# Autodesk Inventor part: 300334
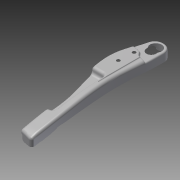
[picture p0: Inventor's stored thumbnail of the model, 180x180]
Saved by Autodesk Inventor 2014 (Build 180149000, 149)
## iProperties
Created: 2007-11
Part Number: 300334
Document SubType Name: Modeling
Designer: TH
Density: 7.85 g/cm^3
Mass: 603.841 g
Surface Area: 1574.23 cm^2
Volume: 76.9224 cm^3
Material: Steel
Description: RIGHT SIDE BACK MEMBER
Appearance: Steel
Component Category: Back Component
Author: TH
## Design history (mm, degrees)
workplane "Work Plane2"
sketch "Sketch2"
  geometry: L1 (50.438, -236.247)-(-305.503, 567.045) reference; L2 (295.506, 71.309)-(-341.064, -210.757) reference; L3 (-55.255, -84.114)-(-67.991, -55.371); L4 (-9.077, -101.935)-(-4.472, -99.894); L5 (15.931, -62.906)-(3.489, 23.045); L6 (-276.253, 429.962)-(-219.046, 442.719); L7 (-219.046, 442.719)-(-213.25, 429.637); L8 (-276.253, 429.962)-(-270.592, 416.127); A1 r 35 centre (-18.708, -67.92) between (-4.472, -99.894) and (15.931, -62.906); A2 r 35 centre (-23.256, -69.935) between (-55.255, -84.114) and (-9.077, -101.935); 10 further points
  constraints: 12 end point, 4 point on circle, 3 tangent, 2 centre point, 2 perpendicular, 2 point on line, 1 parallel, 17 other
  dimensions: "d0" = 35 radius of A2; "d1" = 35 radius of A1; "d2" = 4.97386 distance from line of A1.centre L1; "d4" = 542 distance from line of A1.centre L6; "d110" = 80.3179 deg angle of L8 L6; "d111" = 78.6722 deg angle of L7 L6
extrude "Extrusion1" new body sketch "Sketch2" distance "d5" = 82.31137; taper "d6" = 0 deg
fillet "Fillet1" dims "d7" = 11
workplane "Work Plane3"
sketch "Sketch4"
  geometry: L1 (-74.175, -82.311)-(-533.712, -82.311) reference; L2 (-533.712, 0)-(-533.712, -82.311) reference; L3 (-533.712, 0)-(-74.175, 0) reference; L4 (-74.175, 0)-(-74.175, -82.311) reference; L5 (-556.972, 0)-(-556.972, -82.311) reference; L6 (-556.972, -82.311)-(-556.972, -51.085); L7 (-556.972, -51.085)-(-546.972, -45.311); L8 (-546.972, -45.311)-(-542.696, -44.166); L9 (-549.79, -82.311)-(-556.972, -82.311) reference; L10 (35, 0)-(35, -82.311) reference; L11 (35, 0)-(-224.031, 0); L12 (-224.031, 0)-(-224.031, 20.09); L13 (-224.031, 20.09)-(-556.972, 20.09); L14 (-556.972, -51.085)-(-556.972, 20.09); L15 (-556.972, -51.085)-(-561.972, -53.972); L16 (-561.972, -53.972)-(-561.972, 20.09); L17 (-561.972, 20.09)-(-556.972, 20.09); 6 further points
  constraints: 20 end point, 3 perpendicular, 2 parallel, 2 point on line, 1 collinear, 1 horizontal, 9 other
  dimensions: "d9" = 60 deg angle of L7 L6; "d10" = 10 distance from line of L7.end L5; "d11" = 37 distance from line of L7.end L9; "d12" = 15 deg angle of L7 L8; "d13" = 14.27543 distance from line of L5 L8.end; "d29" = 5 distance between parallel lines of L16 L14
extrude "Extrusion2" cut sketch "Sketch4" stored distance "d14" = 82.31137; taper "d15" = 0 deg
sketch "Sketch5"
  geometry: L1 (-419, -38.349)-(-215.75, -22.71); L2 (-211.5, 0)-(-215.75, -22.71); L3 (-419, -38.349)-(-438.424, -22.843); L4 (-224.031, 0)-(-74.175, 0) reference; L5 (0, 20.844)-(0, -56.014) reference; L6 (-655.497, 0)-(109.25, 0) reference; 2 further points
  constraints: 6 end point, 1 point on line, 2 other
  dimensions: "d16" = 10.6 deg angle of L5 L2; "d17" = 211.5 distance from line of L5 L2.start; "d18" = 215.75 distance from line of L5 L1.end; "d19" = 75 deg angle of L2 L1; "d20" = 43 deg angle of L1 L3; "d21" = 419 distance from line of L5 L1.start
extrude "Extrusion3" cut sketch "Sketch5" distance "d22" = 75; taper "d23" = 0 deg
fillet "Fillet2" dims "d24" = 12
fillet "Fillet3" dims "d25" = 12
fillet "Fillet4" dims "d26" = 12
fillet "Fillet5" dims "d27" = 10
fillet "Fillet6" dims "d28" = 12
sketch "Sketch6"
  geometry: L1 (55.255, 84.114)-(67.991, 55.371) reference; L2 (4.472, 99.894)-(9.077, 101.935) reference; L3 (-3.489, -23.045)-(-15.931, 62.906) reference; L4 (86.496, 10.386)-(50.182, 5.126); L5 (50.182, 5.126)-(30.756, 15.263); L6 (30.756, 15.263)-(-7.798, 6.721); A1 r 35 centre (23.256, 69.935) between (55.255, 84.114) and (9.077, 101.935) reference; A2 r 35 centre (18.708, 67.92) between (4.472, 99.894) and (-15.931, 62.906) reference; 2 further points
  constraints: 6 end point, 1 point on line, 2 other
  dimensions: "d30" = 68 distance from line of L4 point (23.256, 69.935); "d31" = 55 distance from line of A1.centre L6; "d32" = 45 distance from line of A1.centre L5; "d34" = 7.5 horizontal distance of A1.centre L5.end; "d35" = 63.24061 horizontal distance of point (23.256, 69.935) L4.start; "d96" = 64.80946 vertical distance of L4.end A1.centre
extrude "Extrusion4" cut sketch "Sketch6" distance "d36" = 7.2; taper "d37" = 0 deg
fillet "Fillet7" dims "d38" = 12
fillet "Fillet10" dims "d41" = 5
fillet "Fillet11" dims "d42" = 11
fillet "Fillet13" dims "d44" = 4
fillet "Fillet14" dims "d45" = 4
sketch "Sketch7"
  geometry: C1 r 3 at (-8.5, 0); 1 further point
  constraints: 1 centre point
  dimensions: "d47" = 6 diameter of C1; "d48" = 8.5 distance of C1.centre point (0, 0)
extrude "Extrusion5" cut sketch "Sketch7" distance "d49" = 250; taper "d50" = 0 deg
sketch "Sketch9"
  geometry: L1 (0, 98.835)-(0, -16.829) reference; L2 (8.5, 0)-(8.5, 3); L3 (8.5, 0)-(5.5, 0); A1 r 3 centre (8.5, 0) between (8.5, 3) and (5.5, 0); 1 further point
  constraints: 4 end point, 2 point on circle, 1 centre point
  dimensions: "d52" = 3 radius of A1; "d53" = 90 deg angle of L1 L3; "d54" = 90 deg angle of L3 L2
revolve "Revolution1" sketch "Sketch9" stored, may be unused: angle "d55" = 90 deg
fillet "Fillet15" dims "d56" = 2
shell "Shell1" dims "d46" = 1
sketch "Sketch10"
  geometry: L1 (-482.932, -70.761)-(-510.571, -76.746) reference; L2 (-74.175, -82.311)-(-533.712, -82.311) reference; L3 (-539.005, -82.311)-(-549.79, -82.311) reference; L4 (0, -12.2)-(35, -12.2) reference; L5 (0, -12.2)-(0, -82.311) reference; L6 (0, -82.311)-(35, -82.311) reference; L7 (35, -12.2)-(35, -82.311) reference; L8 (35, -42.156)-(32.139, -42.156); L9 (35, -42.156)-(35, -90.815); L10 (35, -90.815)-(-545.613, -90.815); L11 (-545.613, -90.815)-(-545.613, -82.311); 22 further points
  constraints: 8 end point, 4 point on line, 2 perpendicular, 1 horizontal, 1 parallel, 19 other
extrude "Extrusion6" cut sketch "Sketch10" stored distance "d57" = 250; taper "d58" = 0 deg
sketch "Sketch11"
  geometry: L1 (27.137, -86.167)-(27.137, -34.343); L2 (19.355, -26.346)-(-70.705, -23.886); L3 (-72.495, -23.675)-(-114.778, -14.758); L4 (-116.568, -14.547)-(-150.782, -13.612); L5 (-154.205, -14.117)-(-212.597, -33.497); L6 (-213.236, -33.663)-(-224.191, -35.75); L7 (-224.708, -35.82)-(-458.639, -55.447); L8 (-462.612, -56.644)-(-470.617, -61.035); L9 (-473.169, -62.009)-(-531.249, -75.46); L10 (-537.377, -70.589)-(-537.377, -61.915); L11 (-543.505, -57.044)-(-561.7, -61.258); L12 (-561.7, -61.258)-(-561.7, -86.167); L13 (-561.7, -86.167)-(27.137, -86.167); A1 r 5 centre (-532.377, -70.589) between (-537.377, -70.589) and (-531.249, -75.46); A2 r 5 centre (-542.377, -61.915) between (-537.377, -61.915) and (-543.505, -57.044); A3 r 10 centre (-475.426, -52.266) between (-473.169, -62.009) and (-470.617, -61.035); A4 r 10 centre (-457.803, -65.412) between (-458.639, -55.447) and (-462.612, -56.644); A5 r 5 centre (-225.127, -30.838) between (-224.708, -35.82) and (-224.191, -35.75); A6 r 5 centre (-214.172, -28.752) between (-213.236, -33.663) and (-212.597, -33.497); A7 r 10 centre (-116.841, -24.543) between (-114.778, -14.758) and (-116.568, -14.547); A8 r 10 centre (-151.055, -23.608) between (-150.782, -13.612) and (-154.205, -14.117); A9 r 10 centre (-70.432, -13.89) between (-72.495, -23.675) and (-70.705, -23.886); A10 r 8 centre (19.137, -34.343) between (27.137, -34.343) and (19.355, -26.346); 11 further points
  constraints: 26 end point, 20 point on circle, 20 point on line, 20 tangent, 10 centre point, 7 equal radius, 4 parallel, 1 perpendicular, 1 vertical
  dimensions: "d59" = 27.13681 distance from line of L1 point (0, 0); "d60" = 71.60954 horizontal distance of point (-71.61, -23.862) point (0, 0); "d61" = 115.66329 horizontal distance of point (-115.663, -14.571) point (0, 0); "d62" = 152.53802 horizontal distance of point (-152.538, -13.564) point (0, 0); "d63" = 212.91121 horizontal distance of point (-212.911, -33.601) point (0, 0); "d64" = 224.4479 horizontal distance of point (-224.448, -35.799) point (0, 0); "d65" = 460.75226 horizontal distance of point (-460.752, -55.625) point (0, 0); "d66" = 471.82624 horizontal distance of point (0, 0) point (-471.826, -61.697); "d67" = 537.37703 distance from line of point (0, 0) L10; "d68" = 561.70049 distance from line of point (0, 0) L12; "d69" = 26.55872 vertical distance of point (27.137, -26.559) point (0, 0); "d70" = 23.86155 vertical distance of point (0, 0) point (-71.61, -23.862); "d71" = 14.5713 vertical distance of point (0, 0) point (-115.663, -14.571); "d72" = 33.60132 vertical distance of point (-212.911, -33.601) point (0, 0); "d73" = 35.79862 vertical distance of point (0, 0) point (-224.448, -35.799); "d74" = 55.62461 vertical distance of point (0, 0) point (-460.752, -55.625); "d75" = 61.69743 vertical distance of point (0, 0) point (-471.826, -61.697); "d76" = 76.8795 vertical distance of point (-537.377, -76.879) point (0, 0); "d77" = 55.62461 vertical distance of point (0, 0) point (-537.377, -55.625); "d78" = 86.16735 distance from line of point (0, 0) L13; "d79" = 5 radius of A1; "d80" = 10 radius of A3; "d81" = 8 radius of A10
extrude "Extrusion7" cut sketch "Sketch11" distance "d82" = 60; taper "d83" = 0 deg
fillet "Fillet16" dims "d84" = 10
fillet "Fillet17" dims "d85" = 5
fillet "Fillet18" dims "d86" = 5
sketch "Sketch12"
  geometry: L1 (6.502, 95.325)-(11.102, 97.363) reference; L2 (-1.301, 72.381)-(-0.657, 75.267); L3 (3.466, 93.76)-(3.52, 94.004); A1 r 30 centre (18.708, 67.92) between (6.502, 95.325) and (-10.982, 63.623) reference; A2 r 8 centre (14.655, 11.835) between (12.581, 4.108) and (19.522, 5.485) reference; A3 r 8 centre (9.841, 13.126) between (1.921, 14.25) and (7.768, 5.399) reference; A4 r 20.5 centre (18.708, 67.92) between (-1.301, 72.381) and (9.548, 49.581); A5 r 20 centre (33.256, 50.935) between (14.471, 44.068) and (49.563, 62.514); A6 r 24.5 centre (23.256, 69.935) between (47.728, 68.776) and (-0.657, 75.267); A7 r 10 centre (5.079, 40.635) between (14.471, 44.068) and (9.548, 49.581); A8 r 10 centre (57.717, 68.303) between (47.728, 68.776) and (49.563, 62.514); 6 further points
  constraints: 11 point on circle, 8 tangent, 5 centre point, 4 end point, 2 coincident, 1 equal radius, 1 point on line
  dimensions: "d88" = 41 diameter of A4; "d89" = 20 radius of A5; "d90" = 24.5 radius of A6; "d91" = 19 vertical distance of point (23.256, 69.935) A5.centre; "d92" = 10 horizontal distance of A5.centre point (23.256, 69.935); "d93" = 10 radius of A7
extrude "Extrusion8" cut sketch "Sketch12" stored distance "d94" = 60; taper "d95" = 0 deg
sketch "Sketch13"
  geometry: L1 (52.768, -62.685)-(30.582, -3.187); 1 further point
  constraints: 2 end point
  dimensions: "d97" = 63.5 distance of L1.start L1.end; "d98" = 73.12264 vertical distance of point (23.256, 69.935) L1.end; "d99" = 18.68391 distance from line of point (23.256, 69.935) L1; "d100" = 132.62071 vertical distance of point (23.256, 69.935) L1.start
hole "Hole1" sketch "Sketch13" at (52.768, -62.685), (30.582, -3.187) diameter "d101" = 14.65; stored, may be unused: countersink angle "d105" = 90 deg, drill point angle "d107" = 118 deg; dims "d102" = 6, "d103" = 4, "d104" = 2, "d106" = 8
body "Solid1"
node "Projected Loop1"
node "Reference24"
node "Reference25"
node "Reference26"
node "Projected Loop2"
node "Reference27"
node "Reference28"
node "Reference29"
node "Reference30"
node "Reference31"
other parameters: "d8" = -78, "d87" = 49
